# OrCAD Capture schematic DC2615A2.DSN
size Custom
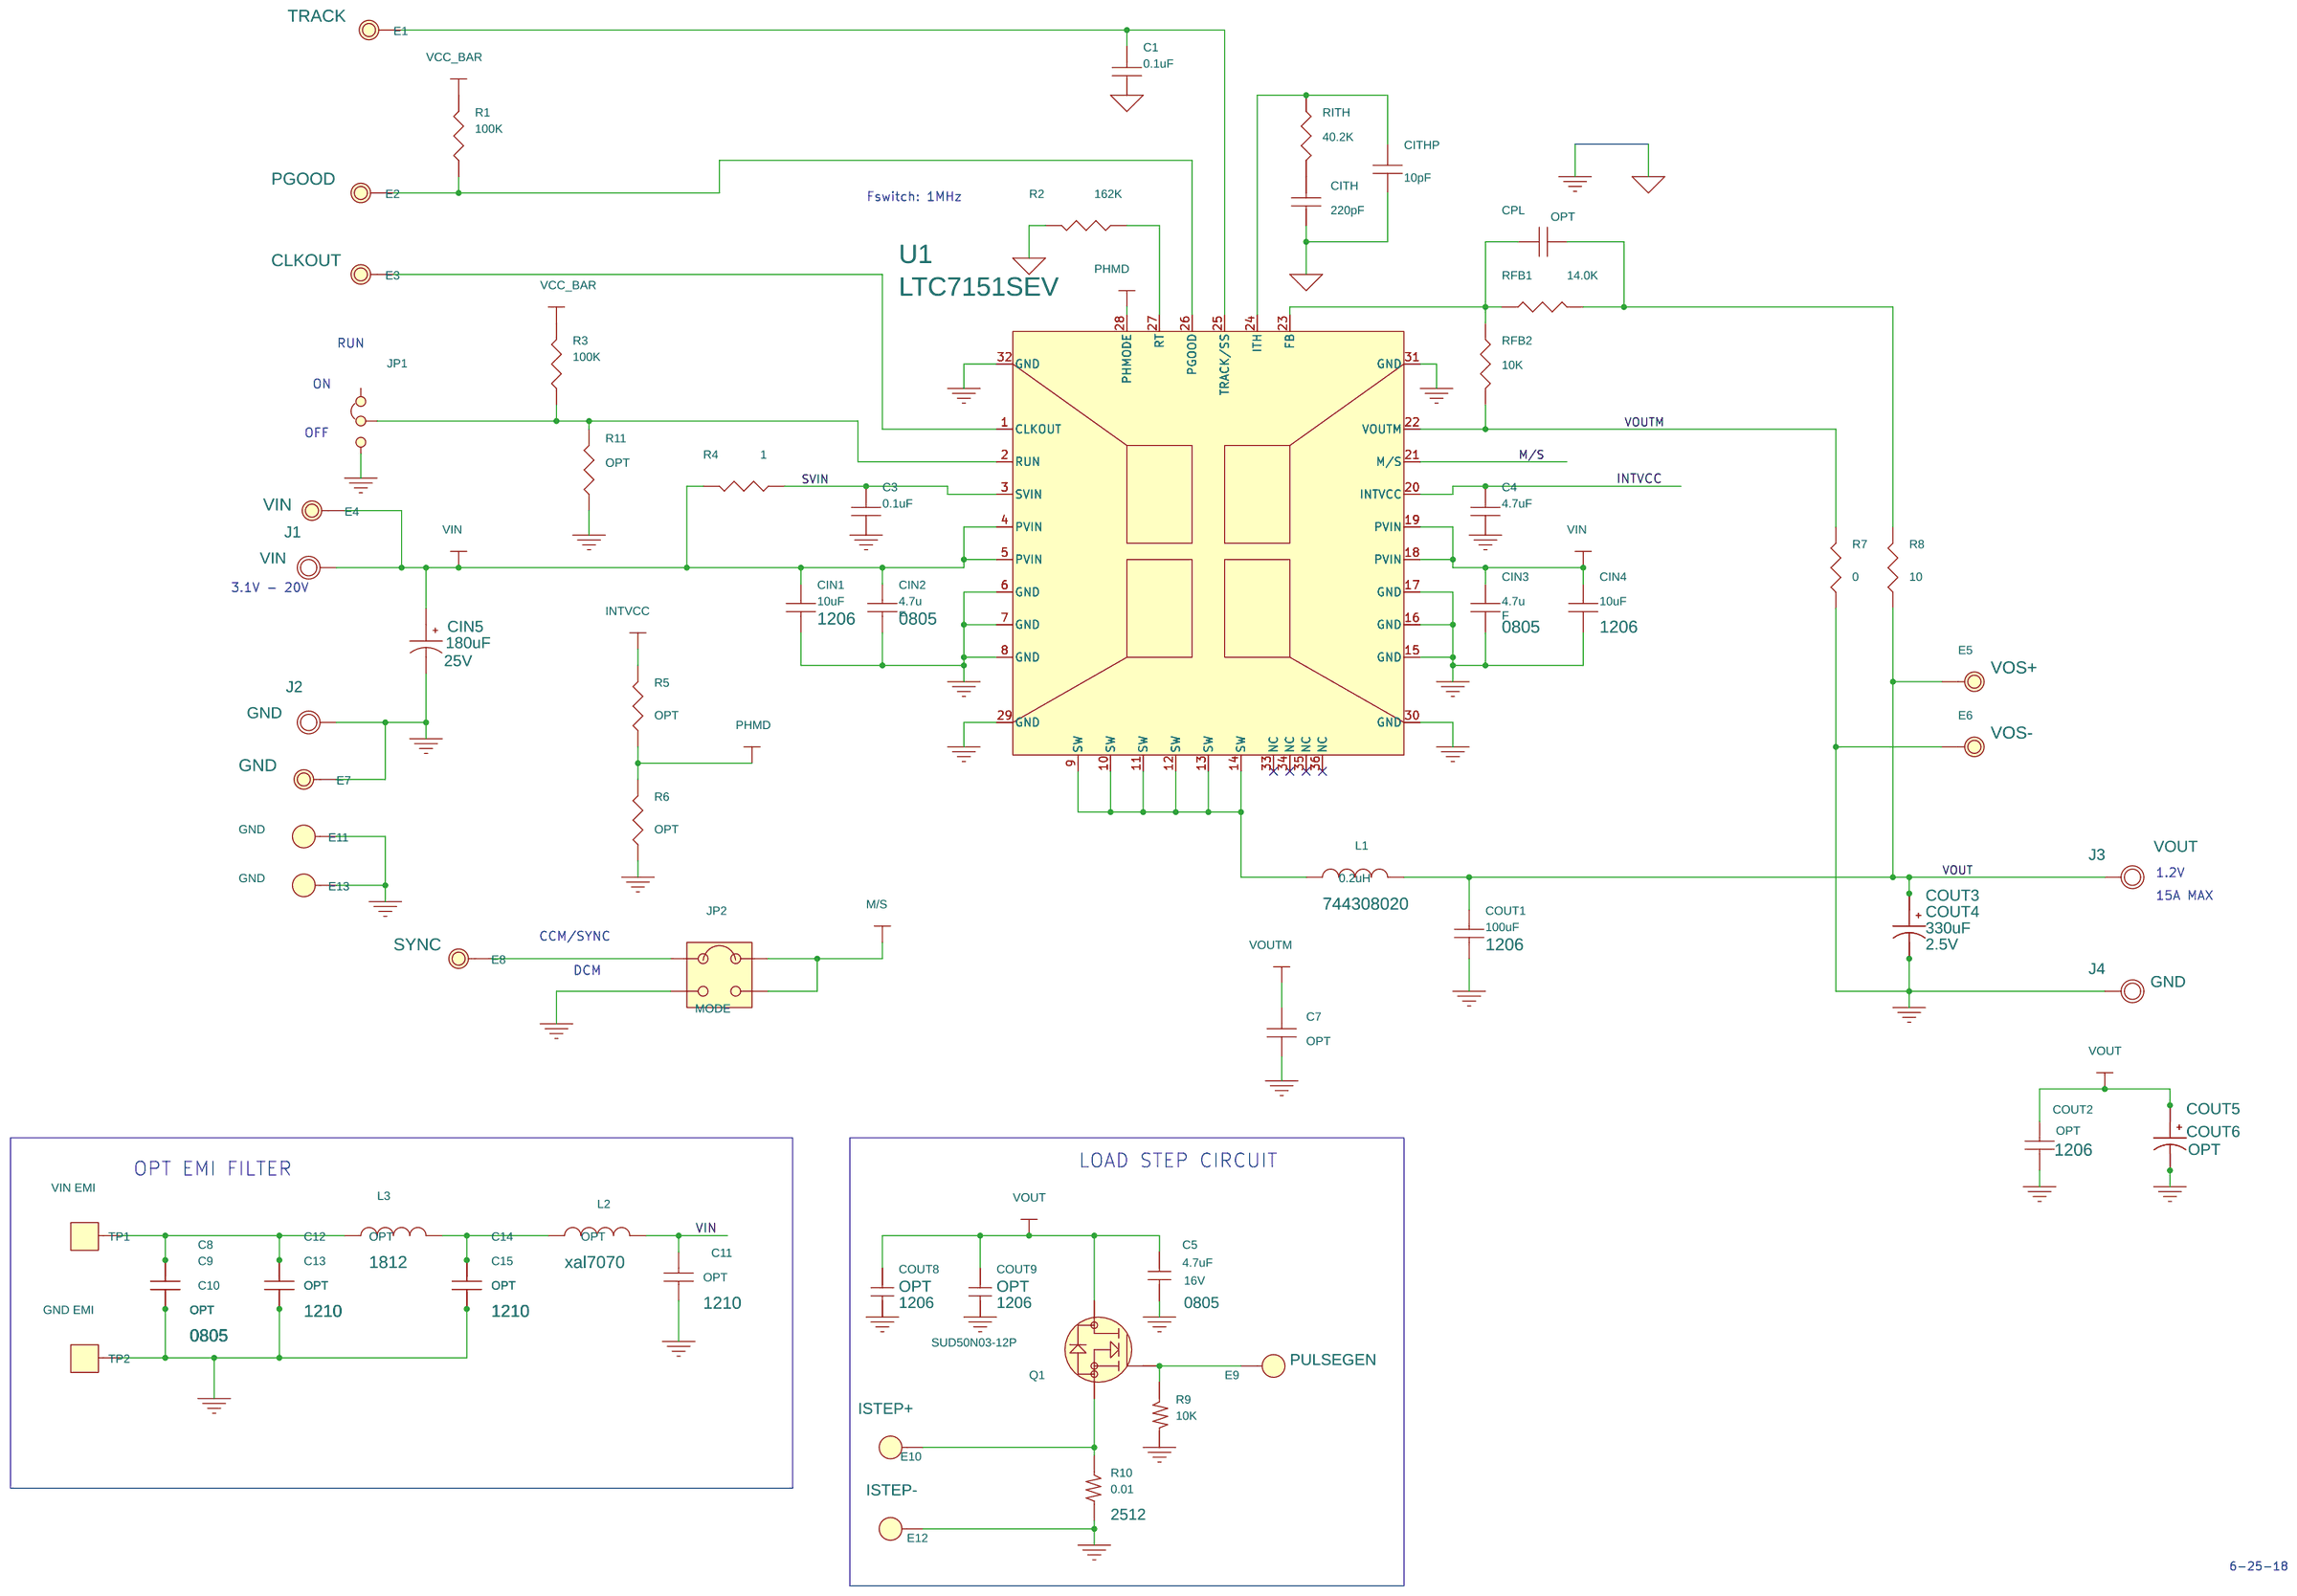
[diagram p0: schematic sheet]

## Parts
C1  0.1uF  [0603]
C3  0.1uF  [0603]
C4  4.7uF  [0603]
C5  4.7uF  [0805]
C7  OPT  [0603]
C8  OPT  [0805]
C9  OPT  [0805]
C10  OPT  [0805]
C11  OPT  [1210]
C12  OPT  [1210]
C13  OPT  [1210]
C14  OPT  [1210]
C15  OPT  [1210]
CIN1  10uF  [1206]
CIN2  4.7u / F  [0805]
CIN3  4.7u / F  [0805]
CIN4  10uF  [1206]
CIN5  180uF  [CAP\SANYO\SVP-F8]
CITH  220pF  [0603]
CITHP  10pF  [0603]
COUT1  100uF  [1206]
COUT2  OPT  [1206]
COUT3  330uF  [7343]
COUT4  330uF  [7343]
COUT5  OPT  [7343]
COUT6  OPT  [7343]
COUT8  C-1206  [1206]
COUT9  C-1206  [1206]
CPL  OPT  [0603]
E1  Testpoint  [PAD150-095]
E2  Testpoint  [PAD150-095]
E3  Testpoint  [PAD150-095]
E4  Testpoint  [PAD150-095]
E5  Testpoint  [PAD150-095]
E6  Testpoint  [PAD150-095]
E7  Testpoint  [PAD150-095]
E8  Testpoint  [PAD150-095]
E9  PAD150-094  [PAD150-095]
E10  PAD150-094  [PAD150-095]
E11  PAD150-094  [PAD150-095]
E12  PAD150-094  [PAD150-095]
E13  PAD150-094  [PAD150-095]
J1  VIN  [KEY-575-4]
J2  GND  [KEY-575-4]
J3  VOUT  [KEY-575-4]
J4  GND  [KEY-575-4]
JP1  JP3X1/079\NO\12  [HD1X3-079]
JP2  MODE  [HDR\2X2\079]
L1  0.2uH  [744308020]
L2  OPT  [xal7070]
L3  OPT  [1812]
Q1  SUD50N03-12P  [TO-252]
R1  100K  [0603]
R2  162K  [0603]
R3  100K  [0603]
R4  1  [0603]
R5  OPT  [0603]
R6  OPT  [0603]
R7  0  [0603]
R8  10  [0603]
R9  10K  [0603]
R10  0.01  [2512]
R11  OPT  [0603]
RFB1  14.0K  [0603]
RFB2  10K  [0603]
RITH  40.2K  [0603]
TP1  PAD150-094  [PAD]
TP2  PAD150-094  [PAD]
U1  LTC7151SEV  [LGA_28_5MMX4MM]

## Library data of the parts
C1 C3 C4 C7-C15 CIN1-CIN4 CITH CITHP COUT1 COUT2 CPL = CAP_NP
C5 = CAP-NP: CAP, 0805 4.7uF 10% 6.3V X5R; Part Number: AVX 08056D475KAT; Voltage: 16V
CIN5 = CAPACITOR_POL: CAP, 180uF 20% 16V; Part Number: SANYO 16SVP180MX; Voltage: 25V
COUT3-COUT6 = t510x337k010as: CAP, 7343 330uF 20% 2.5V POSCAP; 1st Part Field: 2.5V; 3rd Part Field: POSCAP; Part Number: SANYO 2R5TPE330M9
COUT8 COUT9 = CAP-NP: CAP, 1210 47uF 20% 6.3V X5R/100uF 20% 6.3V X5R; COMPFIXED: OPT; Part Number: TDK C3225X5R0J476MT/C3225X5R0J107MT
E1 = MillMax-2501-2_0: V: TRACK
E2 = MillMax-2501-2_0: V: PGOOD
E3 = MillMax-2501-2_0: V: CLKOUT
E4 = MillMax-2501-2_0: V: VIN
E5 = MillMax-2501-2_0: V: VOS+
E6 = MillMax-2501-2_0: V: VOS-
E7 = MillMax-2501-2_0: V: GND
E8 = MillMax-2501-2_0: V: SYNC
E9 = E: COMPFIXED: PULSEGEN; COMPGROUP: GEN
E10 = E: COMPFIXED: ISTEP+
E11 E13 = E: COMPFIXED: GND
E12 = E: COMPFIXED: ISTEP-
J1 J3 = TP_KEY_1502-2_1: JACK, BANANA; Part Number: KEYSTONE 575-4; STATUS: 4.5V - 20V
J2 J4 = TP_KEY_1502-2_1: JACK, BANANA; Part Number: KEYSTONE 575-4
JP1 = JP3X1_079_NO_12
JP2 = CON6AP_7
L1-L3 = INDUCTOR
Q1 = MOSFET_N-DIODE-A_0
R1-R8 R11 RFB1 RFB2 RITH = R_v2
R9 = R: RES, 0603 0 OHM JUMPER; Part Number: PANASONIC ERJ3GEY0R00V
R10 = R: RES, 2010 0.002/0.003 OHMS 5% 1/2W; Part Number: VISHAY WSL20103L000FEA/VISHAY WSL20102L000FEA
TP1 = TP: COMPFIXED: VIN EMI
TP2 = TP: COMPFIXED: GND EMI
U1 = LTC3543EDCB_26

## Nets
GND: C3.1 C4.1 C5.2 C7.1 C8.1 C9.1 C10.1 C11.1 C12.1 C13.1 C14.1 C15.1 CIN1.2 CIN2.2 CIN3.2 CIN4.2 CIN5.2 COUT1.2 COUT2.2 COUT3.2 COUT4.2 COUT5.2 COUT6.2 COUT8.2 COUT9.2 E6.1 E7.1 E11.1(A) E12.1(A) E13.1(A) J2.1 J4.1 JP1.3 JP2.4 R6.1 R7.1 R9.2 R10.2 R11.1 TP2.1(A) U1.6(GND) U1.7(GND) U1.8(GND) U1.15(GND) U1.16(GND) U1.17(GND) U1.29(GND) U1.30(GND) U1.31(GND) U1.32(GND)
SGND: C1.1 CITH.1 CITHP.1 R2.2
SVIN: C3.2 R3.2 R4.1 U1.3(SVIN)
VIN: C11.2 CIN1.1 CIN2.1 CIN3.1 CIN4.1 CIN5.1 E4.1 J1.1 L2.2 R4.2 U1.4(PVIN) U1.5(PVIN) U1.18(PVIN) U1.19(PVIN)
INTVCC: C4.2 R1.2 R5.2 U1.20(INTVCC)
M/S: JP2.1 JP2.3 U1.21(M/S)
PHMD: R5.1 R6.2 U1.28(PHMODE)
VOUT: C5.1 COUT1.1 COUT2.1 COUT3.1 COUT4.1 COUT5.1 COUT6.1 COUT8.1 COUT9.1 E5.1 J3.1 L1.2 Q1.2 R8.1
VOUTM: C7.2 R7.2 RFB2.2 U1.22(VOUTM)
N16471152: CITHP.2 RITH.1 U1.24(ITH)
N16758454: E10.1(A) Q1.3 R10.1
N16758490: E9.1(A) Q1.1 R9.1
N16821363: L1.1 U1.9(SW) U1.10(SW) U1.11(SW) U1.12(SW) U1.13(SW) U1.14(SW)
N16825984: CPL.2 RFB1.1 RFB2.1 U1.23(FB)
N16826321: CPL.1 R8.2 RFB1.2
N16832909: C1.2 E1.1 U1.25(TRACK/SS)
N16833006: JP1.2 R3.1 R11.2 U1.2(RUN)
N16833017: E3.1 U1.1(CLKOUT)
N16833905: E2.1 R1.1 U1.26(PGOOD)
N16834623: R2.1 U1.27(RT)
N16841756: E8.1 JP2.2
N16877235: C8.2 C9.2 C10.2 C12.2 C13.2 L3.1 TP1.1(A)
N16891134: C14.2 C15.2 L2.1 L3.2
N16895032: CITH.2 RITH.2

Not connected (* = marked no-connect by the designer): JP1 1; U1 33(NC)* 34(NC)* 35(NC)* 36(NC)*

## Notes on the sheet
- Fswitch: 1MHz
- RUN
- ON
- OFF
- 3.1V - 20V
- 1.2V
- 15A MAX
- CCM/SYNC
- DCM
- LOAD STEP CIRCUIT
- OPT EMI FILTER
- 6-25-18
